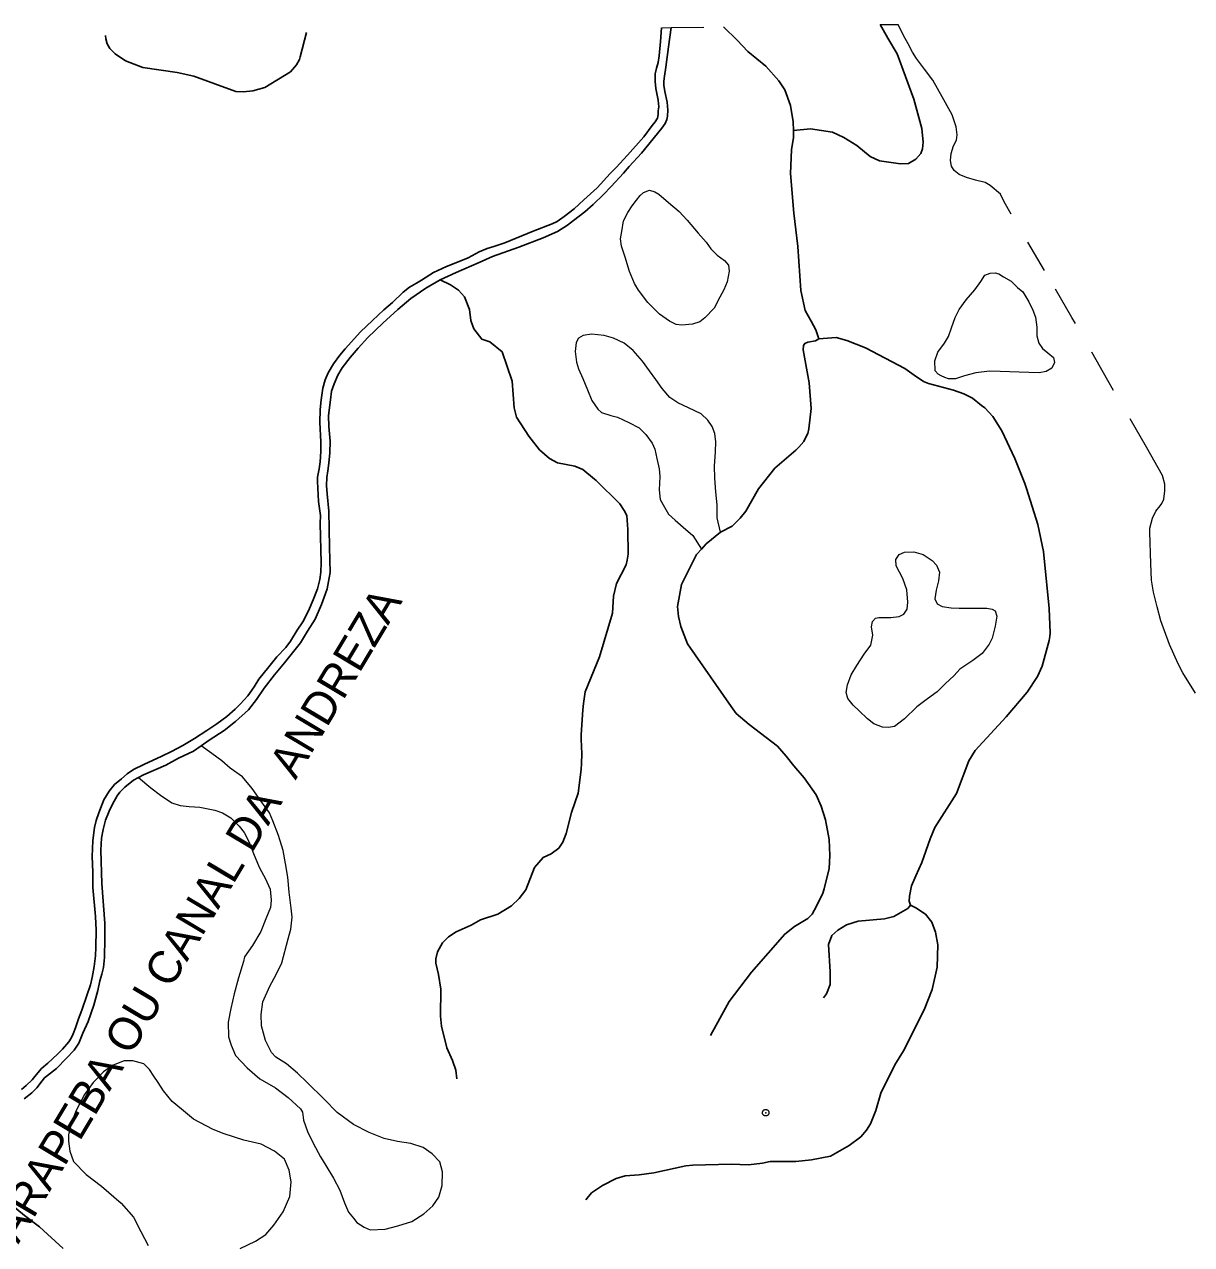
# Model space of a CAD drawing. Extents: x 267.7 to 296, y 7537.7 to 7565.8.
# Drawn here: x 278.742 to 282.305, y 7561.905 to 7565.628 of the extents above; entities that cross this region are included whole.
import ezdxf
from ezdxf.enums import TextEntityAlignment as Align

# ---------------------------------------------------------------- set-up
doc = ezdxf.new("R2010")
doc.units = 0
doc.header["$LTSCALE"] = 0.04
doc.header["$PDMODE"] = 32
doc.header["$PDSIZE"] = 0.02
doc.linetypes.add('SHORT_DASHED', pattern=[2.7, 1.5, -1.2])
for name, color, linetype, lineweight in [('2', 7, 'Continuous', 25), ('21', 7, 'SHORT_DASHED', 13), ('62', 7, 'SHORT_DASHED', 13), ('7', 7, 'Continuous', 25)]:
    doc.layers.add(name, color=color, linetype=linetype, lineweight=lineweight)
doc.layers.add('61', color=7, linetype='Continuous')

msp = doc.modelspace()

# ---------------------------------------------------------------- linework, layer by layer
at = {"layer": '2'}
for points in [[(280.6871, 7565.6181), (280.6839, 7565.5761), (280.6797, 7565.5324), (280.6765, 7565.5116), (280.6711, 7565.4946), (280.6674, 7565.4776), (280.6669, 7565.4541), (280.669, 7565.4323), (280.6765, 7565.3966), (280.6781, 7565.3769), (280.677, 7565.3646), (280.677, 7565.3534), (280.6743, 7565.3422), (280.6669, 7565.3305), (280.6584, 7565.3193), (280.6323, 7565.2852), (280.5827, 7565.2293), (280.548, 7565.1917), (280.5305, 7565.1728), (280.4905, 7565.1297), (280.4501, 7565.0924), (280.4202, 7565.0652), (280.3893, 7565.0423), (280.3685, 7565.0269), (280.3531, 7565.0199), (280.295, 7564.997), (280.2082, 7564.9619), (280.1752, 7564.9507), (280.1544, 7564.9448), (280.1304, 7564.9342), (280.0963, 7564.916), (280.0585, 7564.9006), (280.0303, 7564.8894), (279.9903, 7564.8708), (279.9546, 7564.8478), (279.9392, 7564.8388), (279.9178, 7564.826), (279.8981, 7564.8116), (279.8656, 7564.7797), (279.839, 7564.7573), (279.8044, 7564.7248), (279.7681, 7564.6896), (279.7207, 7564.6379), (279.7053, 7564.6193), (279.6856, 7564.5921), (279.6696, 7564.565), (279.66, 7564.5431), (279.6531, 7564.5186), (279.6483, 7564.4829), (279.6445, 7564.4526), (279.644, 7564.4131), (279.6467, 7564.3545), (279.6467, 7564.3252), (279.6451, 7564.2933), (279.6413, 7564.272), (279.6371, 7564.2469), (279.6366, 7564.2331), (279.6398, 7564.1723), (279.6456, 7564.1292), (279.6451, 7564.1047), (279.6477, 7563.9848), (279.6472, 7563.9571), (279.644, 7563.9342), (279.6366, 7563.9054), (279.6238, 7563.8719), (279.6094, 7563.8383), (279.5918, 7563.8047), (279.5748, 7563.7792), (279.554, 7563.7461), (279.5396, 7563.7264), (279.513, 7563.6982), (279.4879, 7563.6678), (279.4576, 7563.63), (279.4437, 7563.6071), (279.424, 7563.5794), (279.4021, 7563.5549), (279.3856, 7563.5384), (279.3595, 7563.5165), (279.3297, 7563.4936), (279.2993, 7563.4734), (279.2615, 7563.4494), (279.2253, 7563.4276), (279.1906, 7563.4094), (279.1613, 7563.3956), (279.107, 7563.37), (279.0756, 7563.354), (279.0553, 7563.3413), (279.0383, 7563.3263), (279.0175, 7563.3088), (279.0005, 7563.2885), (278.985, 7563.2624), (278.969, 7563.2219), (278.961, 7563.1985), (278.9562, 7563.1772), (278.9514, 7563.1383)], [(280.7159, 7565.6185), (280.7084, 7565.5601), (280.7004, 7565.4978), (280.6962, 7565.4701), (280.6935, 7565.4546), (280.6935, 7565.4424), (280.6972, 7565.4237), (280.7042, 7565.3912), (280.7058, 7565.3667), (280.7047, 7565.3486), (280.7026, 7565.338), (280.6978, 7565.3263), (280.6877, 7565.3119), (280.6259, 7565.2352), (280.588, 7565.1941), (280.5703, 7565.1747), (280.5332, 7565.1339), (280.5097, 7565.1089), (280.4778, 7565.0791), (280.4522, 7565.0562), (280.4186, 7565.03), (280.4, 7565.0157), (280.3696, 7564.9965), (280.3259, 7564.9768), (280.2513, 7564.948), (280.1704, 7564.9198), (280.1299, 7564.9017), (280.0601, 7564.8713), (280.0115, 7564.8483)], [(280.0115, 7564.8483), (279.9674, 7564.8233), (279.9216, 7564.7914), (279.8816, 7564.7583), (279.8363, 7564.7163), (279.79, 7564.6731), (279.7607, 7564.6406), (279.7362, 7564.6118), (279.7117, 7564.5804), (279.6984, 7564.558), (279.6872, 7564.5314), (279.6797, 7564.5085), (279.676, 7564.4824), (279.6707, 7564.4344), (279.6717, 7564.4009), (279.6754, 7564.3561), (279.6744, 7564.3204), (279.6712, 7564.2895), (279.6685, 7564.2661), (279.6648, 7564.2458), (279.6643, 7564.2213), (279.6659, 7564.1952), (279.6712, 7564.143), (279.6738, 7564.0328), (279.6749, 7563.9555), (279.6728, 7563.939), (279.6664, 7563.906), (279.6611, 7563.8916), (279.6488, 7563.858), (279.6291, 7563.8133), (279.6067, 7563.7765), (279.5849, 7563.7408), (279.5359, 7563.6795), (279.5055, 7563.6438), (279.4741, 7563.6028), (279.4506, 7563.5677), (279.4256, 7563.5368), (279.3867, 7563.5011), (279.3521, 7563.4739), (279.3057, 7563.4435), (279.2817, 7563.427)], [(279.2817, 7563.427), (279.2578, 7563.4105), (279.212, 7563.3892), (279.1736, 7563.3679), (279.1059, 7563.3386), (279.0908, 7563.3303)], [(279.0908, 7563.3303), (279.0756, 7563.3221), (279.0489, 7563.3002), (279.033, 7563.2858), (279.0255, 7563.2741), (279.0111, 7563.2491), (279.0005, 7563.2272), (278.9898, 7563.1995), (278.9829, 7563.1713), (278.9776, 7563.1452), (278.9749, 7563.1084), (278.9786, 7563.0067), (278.9871, 7562.8852), (278.9877, 7562.8394), (278.9861, 7562.7803), (278.9839, 7562.7499), (278.9786, 7562.7297), (278.9722, 7562.7094), (278.9658, 7562.6801), (278.9536, 7562.6354), (278.9365, 7562.5853), (278.9205, 7562.5501), (278.9078, 7562.5192), (278.8939, 7562.4985), (278.871, 7562.4734), (278.8396, 7562.4425), (278.8033, 7562.4137), (278.7964, 7562.4047), (278.7804, 7562.3834), (278.765, 7562.3674), (278.7415, 7562.3498)], [(278.9514, 7563.1383), (278.9493, 7563.0893), (278.9514, 7563.0413), (278.9509, 7562.9944), (278.9589, 7562.906), (278.961, 7562.8644)], [(278.961, 7562.8644), (278.9605, 7562.8122), (278.9594, 7562.7856), (278.9552, 7562.7536), (278.9493, 7562.7195), (278.9435, 7562.6972), (278.9328, 7562.6652), (278.9174, 7562.6204), (278.9072, 7562.5938), (278.8982, 7562.5666), (278.8907, 7562.5475), (278.8849, 7562.5347), (278.8779, 7562.523), (278.8587, 7562.5011), (278.8433, 7562.4862), (278.814, 7562.4585), (278.7943, 7562.442), (278.7783, 7562.4223), (278.7655, 7562.4074), (278.7474, 7562.3898), (278.7336, 7562.3781)]]:
    msp.add_lwpolyline(points, dxfattribs=at)
at = {"layer": '21'}
for points in [[(281.5716, 7565.1961), (281.569, 7565.2129), (281.5707, 7565.234), (281.5775, 7565.2575), (281.5867, 7565.2752), (281.5892, 7565.2912), (281.5859, 7565.3156), (281.5741, 7565.3518), (281.5438, 7565.4073), (281.5152, 7565.4578), (281.4899, 7565.4914), (281.4647, 7565.5243), (281.4529, 7565.5436), (281.4395, 7565.5689), (281.4252, 7565.5941), (281.4091, 7565.6282)], [(281.6751, 7565.1456), (281.6456, 7565.1532), (281.6178, 7565.1608), (281.5951, 7565.17), (281.58, 7565.1826), (281.5716, 7565.1961)], [(282.3163, 7563.5872), (282.2784, 7563.6495), (282.2641, 7563.6773), (282.2372, 7563.7362), (282.2111, 7563.8085), (282.2001, 7563.8506), (282.1884, 7563.8952), (282.1825, 7563.9322), (282.1799, 7563.9836), (282.1774, 7564.0786), (282.1774, 7564.0913), (282.185, 7564.1216), (282.1959, 7564.1426), (282.2085, 7564.1594), (282.2136, 7564.1666), (282.2201, 7564.1799), (282.2227, 7564.2049), (282.2227, 7564.2253), (282.2162, 7564.2512), (282.1669, 7564.3377), (282.0492, 7564.5412), (281.9394, 7564.7342), (281.8562, 7564.8776), (281.7323, 7565.0864), (281.721, 7565.1097), (281.6897, 7565.1361), (281.6751, 7565.1456)], [(280.8672, 7564.0791), (280.8571, 7564.1229), (280.8571, 7564.1625), (280.8527, 7564.2021), (280.8498, 7564.2431), (280.8483, 7564.2798), (280.8513, 7564.3237), (280.8527, 7564.3545), (280.8498, 7564.3795), (280.841, 7564.4014), (280.8278, 7564.4205), (280.8073, 7564.4396), (280.7692, 7564.4586), (280.7369, 7564.4733), (280.712, 7564.4894), (280.6885, 7564.5173), (280.6695, 7564.5451), (280.6504, 7564.5715), (280.6284, 7564.6008), (280.6006, 7564.6331), (280.5727, 7564.6551), (280.5405, 7564.6712), (280.5112, 7564.6785), (280.473, 7564.6829), (280.4481, 7564.6785), (280.4334, 7564.6712), (280.4261, 7564.658), (280.4232, 7564.6302), (280.4276, 7564.5979), (280.4334, 7564.5774), (280.4466, 7564.5481), (280.4613, 7564.5129), (280.4745, 7564.4806), (280.4921, 7564.4542), (280.5038, 7564.444), (280.5317, 7564.4352), (280.5522, 7564.4293), (280.5874, 7564.4132), (280.6182, 7564.397), (280.6387, 7564.3765), (280.6578, 7564.3501), (280.6666, 7564.3325), (280.6724, 7564.3032), (280.6797, 7564.2724), (280.6812, 7564.249), (280.6797, 7564.2079), (280.6827, 7564.1786), (280.6959, 7564.1551), (280.7076, 7564.1332), (280.7281, 7564.1156), (280.7531, 7564.0936), (280.7824, 7564.0686), (280.8084, 7564.0269)], [(279.7973, 7561.9502), (279.8431, 7561.9515), (279.8824, 7561.9619), (279.9242, 7561.975), (279.9609, 7561.9986), (279.9884, 7562.0234), (280.0067, 7562.0496), (280.0172, 7562.085), (280.0185, 7562.1268), (280.0106, 7562.1569), (279.9871, 7562.1818), (279.9596, 7562.2014), (279.9216, 7562.2132), (279.881, 7562.2198), (279.8405, 7562.2289), (279.7947, 7562.2472), (279.7462, 7562.2708), (279.6965, 7562.3074), (279.6573, 7562.348), (279.6049, 7562.3991), (279.5761, 7562.4279), (279.5421, 7562.4566), (279.5094, 7562.4763), (279.4963, 7562.4907), (279.478, 7562.5273), (279.4662, 7562.5718), (279.4649, 7562.6072), (279.4701, 7562.6451), (279.491, 7562.6935), (279.5107, 7562.7289), (279.5277, 7562.7642), (279.5473, 7562.8375), (279.5552, 7562.8676), (279.5591, 7562.9042), (279.5565, 7562.9317), (279.5499, 7562.9801), (279.546, 7563.026), (279.5395, 7563.0678), (279.5316, 7563.1071), (279.5172, 7563.1529), (279.5002, 7563.1974), (279.4897, 7563.2223), (279.4636, 7563.2589), (279.4374, 7563.2969), (279.4073, 7563.3322), (279.3706, 7563.3584), (279.3445, 7563.3806), (279.3144, 7563.4029), (279.2817, 7563.427)], [(279.0908, 7563.3303), (279.1285, 7563.2982), (279.1573, 7563.2759), (279.1926, 7563.2524), (279.2175, 7563.2445), (279.245, 7563.2419), (279.2777, 7563.2393), (279.3235, 7563.2301), (279.3471, 7563.2223), (279.3719, 7563.2066), (279.3981, 7563.1817), (279.4125, 7563.1621), (279.4269, 7563.1346), (279.4439, 7563.0927), (279.457, 7563.0613), (279.4609, 7563.0521), (279.4766, 7563.0233), (279.4923, 7562.9893), (279.495, 7562.9553), (279.4937, 7562.933), (279.4793, 7562.899), (279.4636, 7562.8597), (279.4387, 7562.8179), (279.4138, 7562.7825), (279.4112, 7562.7681), (279.3955, 7562.7184), (279.3824, 7562.67), (279.3719, 7562.6255), (279.3641, 7562.5836), (279.3654, 7562.5391), (279.3733, 7562.5129), (279.3863, 7562.4815), (279.4217, 7562.4436), (279.4609, 7562.4108), (279.5081, 7562.3834), (279.5473, 7562.3533), (279.5853, 7562.3192), (279.5905, 7562.3088), (279.5944, 7562.2839), (279.6062, 7562.2499), (279.6232, 7562.2145), (279.6455, 7562.1726), (279.6625, 7562.1465), (279.686, 7562.1072), (279.7044, 7562.0706), (279.7188, 7562.0326), (279.7318, 7562.0038), (279.7462, 7561.9855), (279.7567, 7561.9724), (279.779, 7561.958), (279.7973, 7561.9502)], [(279.4009, 7561.8924), (279.4477, 7561.9149), (279.4795, 7561.9355), (279.5039, 7561.9636), (279.532, 7562.0048), (279.5526, 7562.0516), (279.5563, 7562.0965), (279.5507, 7562.1321), (279.5357, 7562.1658), (279.5058, 7562.1901), (279.4646, 7562.2107), (279.4121, 7562.2238), (279.3522, 7562.2426), (279.3185, 7562.2557), (279.2586, 7562.2875), (279.2212, 7562.3175), (279.1931, 7562.3418), (279.1669, 7562.3736), (279.15, 7562.3998), (279.1369, 7562.4186), (279.1238, 7562.4392), (279.1069, 7562.456), (279.0732, 7562.4654), (279.047, 7562.4654), (279.0133, 7562.4523), (278.9834, 7562.4317), (278.9515, 7562.3998), (278.9253, 7562.3624), (278.8991, 7562.3118), (278.886, 7562.2763), (278.8766, 7562.2407), (278.8766, 7562.2201), (278.8804, 7562.1901), (278.8916, 7562.1583), (278.9309, 7562.119), (278.9777, 7562.0834), (279.0377, 7562.031), (279.0751, 7561.9879), (279.0976, 7561.9448), (279.12, 7561.9018)]]:
    msp.add_lwpolyline(points, dxfattribs=at)
for points in [[(280.6803, 7564.7437), (280.6453, 7564.7794), (280.6169, 7564.8168), (280.6047, 7564.838), (280.5893, 7564.8745), (280.5763, 7564.9176), (280.5649, 7564.9518), (280.5616, 7564.9737), (280.5658, 7564.9964), (280.5709, 7565.0292), (280.5835, 7565.0544), (280.5974, 7565.0746), (280.61, 7565.0922), (280.6213, 7565.1061), (280.6314, 7565.1149), (280.6503, 7565.1225), (280.6667, 7565.1175), (280.6781, 7565.1099), (280.7083, 7565.0847), (280.7411, 7565.0569), (280.7651, 7565.0305), (280.7991, 7564.9914), (280.8231, 7564.9636), (280.8369, 7564.9434), (280.8571, 7564.9245), (280.8786, 7564.9081), (280.8912, 7564.893), (280.8937, 7564.8754), (280.8874, 7564.8426), (280.8773, 7564.8186), (280.8647, 7564.7959), (280.847, 7564.7619), (280.8193, 7564.7329), (280.8042, 7564.7203), (280.7815, 7564.7139), (280.7487, 7564.7102), (280.731, 7564.7127), (280.7108, 7564.7228)], [(281.5403, 7564.5558), (281.5312, 7564.5604), (281.5221, 7564.5713), (281.5212, 7564.6013), (281.5303, 7564.6276), (281.5503, 7564.6558), (281.563, 7564.6757), (281.5721, 7564.7021), (281.583, 7564.7339), (281.5948, 7564.7584), (281.6166, 7564.7875), (281.6429, 7564.8183), (281.6611, 7564.8438), (281.6738, 7564.8628), (281.6902, 7564.8692), (281.7047, 7564.8701), (281.7165, 7564.8674), (281.7301, 7564.8583), (281.7538, 7564.8447), (281.7728, 7564.8256), (281.7892, 7564.812), (281.8082, 7564.7811), (281.8201, 7564.7557), (281.8282, 7564.7348), (281.8319, 7564.7039), (281.8319, 7564.6776), (281.8382, 7564.6558), (281.8491, 7564.6394), (281.8655, 7564.6258), (281.8827, 7564.6122), (281.8864, 7564.5967), (281.8782, 7564.5795), (281.8609, 7564.5686), (281.8391, 7564.5649), (281.8082, 7564.5658), (281.7201, 7564.5695), (281.6874, 7564.5704), (281.6457, 7564.5649), (281.6112, 7564.5558), (281.5839, 7564.5468), (281.563, 7564.5468), (281.5512, 7564.5504)], [(281.3151, 7563.5094), (281.2905, 7563.534), (281.2717, 7563.5504), (281.2553, 7563.5715), (281.2506, 7563.5891), (281.2541, 7563.6125), (281.2658, 7563.643), (281.2834, 7563.6723), (281.3057, 7563.7062), (281.3256, 7563.7344), (281.3315, 7563.7648), (281.3279, 7563.7894), (281.3303, 7563.8058), (281.3397, 7563.8164), (281.3502, 7563.8187), (281.3865, 7563.8187), (281.4123, 7563.8211), (281.4264, 7563.8281), (281.4369, 7563.8433), (281.4381, 7563.8656), (281.4357, 7563.9031), (281.4229, 7563.9371), (281.4029, 7563.9757), (281.4018, 7563.9957), (281.4123, 7564.0109), (281.4287, 7564.0179), (281.4568, 7564.0191), (281.485, 7564.0109), (281.5131, 7563.9921), (281.526, 7563.9781), (281.5353, 7563.957), (281.5318, 7563.93), (281.5248, 7563.9019), (281.5213, 7563.875), (281.5283, 7563.8597), (281.5435, 7563.8515), (281.5705, 7563.848), (281.5951, 7563.8469), (281.6314, 7563.8469), (281.6795, 7563.8469), (281.6959, 7563.8433), (281.7052, 7563.8387), (281.7099, 7563.8222), (281.7052, 7563.7918), (281.6959, 7563.7555), (281.6865, 7563.7367), (281.6654, 7563.7086), (281.6373, 7563.6875), (281.5974, 7563.6606), (281.5799, 7563.6418), (281.5529, 7563.616), (281.5283, 7563.5914), (281.499, 7563.5703), (281.4662, 7563.5457), (281.4287, 7563.5094), (281.3983, 7563.486), (281.3795, 7563.4825), (281.3608, 7563.4836), (281.335, 7563.4942)]]:
    msp.add_lwpolyline(points, close=True, dxfattribs=at)
msp.add_point((281.0048, 7562.3072), dxfattribs=at)
at = {"layer": '62'}
for p, q in [((280.6871, 7565.6181), (280.7159, 7565.6185)), ((280.7159, 7565.6185), (280.8761, 7565.6207))]:
    msp.add_line(p, q, dxfattribs=at)
msp.add_lwpolyline([(281.3537, 7565.6274), (281.4005, 7565.6281), (281.4091, 7565.6282)], dxfattribs=at)
at = {"layer": '7'}
for points in [[(279.6029, 7565.6031), (279.5835, 7565.5295), (279.5813, 7565.5213), (279.5723, 7565.505), (279.5543, 7565.4834), (279.4755, 7565.4361), (279.4398, 7565.4255), (279.4106, 7565.4225), (279.3878, 7565.4239), (279.2594, 7565.4703), (279.208, 7565.4813), (279.1032, 7565.497), (279.051, 7565.5172), (279.0191, 7565.5386), (279.0026, 7565.5547), (278.9947, 7565.5685), (278.991, 7565.5842), (278.9893, 7565.5944)], [(281.0895, 7565.3043), (281.0889, 7565.3313), (281.0807, 7565.3806), (281.063, 7565.4281), (281.0449, 7565.456), (281.0048, 7565.5007), (280.9504, 7565.5458), (280.9176, 7565.5802), (280.8761, 7565.6207)], [(281.3537, 7565.6274), (281.3779, 7565.5861), (281.4059, 7565.5383), (281.4567, 7565.3997), (281.4818, 7565.3103), (281.4855, 7565.2689), (281.4838, 7565.2484), (281.4779, 7565.2338), (281.4625, 7565.2174), (281.441, 7565.204), (281.4164, 7565.203), (281.3517, 7565.2122), (281.3239, 7565.2247), (281.2829, 7565.2584), (281.2433, 7565.2833), (281.2082, 7565.2991), (281.141, 7565.3092), (281.0895, 7565.3043)], [(281.1669, 7564.6689), (281.1582, 7564.696), (281.1437, 7564.7221), (281.1253, 7564.7553), (281.1124, 7564.8165), (281.1028, 7564.9501), (281.0903, 7565.0521), (281.0808, 7565.1736), (281.0834, 7565.2459), (281.0899, 7565.2826), (281.0895, 7565.3043)], [(280.0615, 7562.4101), (280.0594, 7562.4368), (280.0492, 7562.4666), (280.0319, 7562.5056), (280.0153, 7562.5716), (280.0126, 7562.602), (280.0133, 7562.6842), (280.0061, 7562.7293), (279.9979, 7562.7632), (279.9978, 7562.7765), (280.003, 7562.7981), (280.0184, 7562.8258), (280.0369, 7562.8437), (280.06, 7562.8594), (280.106, 7562.8795), (280.134, 7562.8961), (280.1869, 7562.9131), (280.2289, 7562.9387), (280.2524, 7562.9613), (280.2722, 7562.987), (280.2993, 7563.0553), (280.3119, 7563.0711), (280.3253, 7563.0855), (280.3499, 7563.0968), (280.3737, 7563.1148), (280.3858, 7563.1327), (280.3958, 7563.1587), (280.4115, 7563.2231), (280.4325, 7563.282), (280.4414, 7563.3545), (280.4422, 7563.3728), (280.4436, 7563.4021), (280.4418, 7563.4474), (280.4413, 7563.4607), (280.4469, 7563.5362), (280.4483, 7563.5557), (280.4539, 7563.5912), (280.4979, 7563.6988), (280.5373, 7563.8318), (280.5398, 7563.8837), (280.5498, 7563.9216), (280.5789, 7563.979), (280.5816, 7563.993), (280.5851, 7564.0113), (280.5843, 7564.0864), (280.5804, 7564.1298), (280.5727, 7564.145), (280.5593, 7564.1653), (280.4873, 7564.2361), (280.4818, 7564.2407), (280.4463, 7564.27), (280.4225, 7564.2799), (280.3688, 7564.2903), (280.3448, 7564.3033), (280.3148, 7564.3295), (280.2822, 7564.3715), (280.2443, 7564.4292), (280.2375, 7564.458), (280.2308, 7564.54), (280.2, 7564.629), (280.1629, 7564.6599), (280.138, 7564.6674), (280.1134, 7564.6992), (280.1055, 7564.7211), (280.1043, 7564.7245), (280.1011, 7564.7586), (280.0855, 7564.7973), (280.0669, 7564.817), (280.0428, 7564.8331), (280.0115, 7564.8483)], [(280.8672, 7564.0791), (280.9021, 7564.0975), (280.9269, 7564.1211), (280.944, 7564.1431), (280.9823, 7564.2108), (281.0331, 7564.2737), (281.0963, 7564.3294), (281.1059, 7564.3378), (281.1207, 7564.3552), (281.1245, 7564.3628), (281.1331, 7564.3798), (281.1366, 7564.3941), (281.1435, 7564.4557), (281.1371, 7564.5344), (281.1195, 7564.6347), (281.1197, 7564.6487), (281.1238, 7564.6549), (281.1331, 7564.659), (281.1567, 7564.6631), (281.1669, 7564.6689)], [(281.4465, 7562.9403), (281.443, 7562.9531), (281.4441, 7562.9675), (281.4502, 7562.9993), (281.4625, 7563.0301), (281.481, 7563.0711), (281.5067, 7563.143), (281.5213, 7563.1778), (281.5872, 7563.281), (281.6247, 7563.3811), (281.6437, 7563.4129), (281.7384, 7563.5151), (281.8024, 7563.5905), (281.8347, 7563.6381), (281.8488, 7563.6694), (281.8703, 7563.7477), (281.8719, 7563.76), (281.8735, 7563.7717), (281.8704, 7563.846), (281.8528, 7564.0201), (281.8351, 7564.1017), (281.8009, 7564.2124), (281.7956, 7564.2272), (281.792, 7564.2371), (281.7653, 7564.3039), (281.7253, 7564.388), (281.698, 7564.4312), (281.6731, 7564.4583), (281.6639, 7564.4655), (281.6355, 7564.4877), (281.609, 7564.5013), (281.5775, 7564.5122), (281.5015, 7564.5327), (281.4866, 7564.5388), (281.4574, 7564.5574), (281.4298, 7564.5783), (281.309, 7564.6413), (281.2527, 7564.664), (281.2199, 7564.6729), (281.1669, 7564.6689)], [(280.8084, 7564.0269), (280.8156, 7564.0346), (280.8233, 7564.0429), (280.8672, 7564.0791)], [(280.8362, 7562.5427), (280.8933, 7562.6465), (280.961, 7562.7362), (281.0629, 7562.8522), (281.0928, 7562.8749), (281.133, 7562.8995), (281.1466, 7562.9129), (281.1601, 7562.9375), (281.1788, 7562.9774), (281.1831, 7562.9904), (281.198, 7563.052), (281.2005, 7563.0916), (281.1988, 7563.1409), (281.1875, 7563.2005), (281.1736, 7563.243), (281.1587, 7563.2774), (281.1217, 7563.3291), (281.091, 7563.3657), (281.0672, 7563.395), (281.0407, 7563.4252), (280.9545, 7563.492), (280.9142, 7563.5258), (280.8993, 7563.5471), (280.7662, 7563.7381), (280.746, 7563.7912), (280.7383, 7563.8214), (280.7351, 7563.8519), (280.7481, 7563.9186), (280.7934, 7564.0109), (280.8084, 7564.0269)], [(280.4558, 7562.041), (280.4731, 7562.0622), (280.5067, 7562.0852), (280.548, 7562.1063), (280.5757, 7562.1145), (280.6185, 7562.1172), (280.663, 7562.1238), (280.7611, 7562.1449), (280.782, 7562.1474), (280.8991, 7562.1501), (280.9521, 7562.1482), (280.9945, 7562.1535), (281.0184, 7562.1578), (281.0965, 7562.1585), (281.1441, 7562.1633), (281.2023, 7562.1742), (281.2234, 7562.1864), (281.2593, 7562.2069), (281.2951, 7562.2339), (281.3126, 7562.2535), (281.3247, 7562.2737), (281.3412, 7562.3135), (281.3561, 7562.3672), (281.3985, 7562.4536), (281.4256, 7562.4963), (281.488, 7562.6206), (281.5125, 7562.6831), (281.5276, 7562.7512), (281.5299, 7562.8193), (281.5235, 7562.8579), (281.5123, 7562.8888), (281.4926, 7562.9127), (281.4633, 7562.9327), (281.4465, 7562.9403)], [(281.181, 7562.6573), (281.1901, 7562.6695), (281.2016, 7562.6982), (281.2016, 7562.7367), (281.1961, 7562.8206), (281.2071, 7562.8482), (281.2248, 7562.8644), (281.2516, 7562.8806), (281.2873, 7562.8915), (281.3671, 7562.8986), (281.396, 7562.9056), (281.4381, 7562.9304), (281.4465, 7562.9403)], [(278.8606, 7561.8928), (278.7877, 7561.9585), (278.7425, 7561.9934), (278.6656, 7562.056)]]:
    msp.add_lwpolyline(points, dxfattribs=at)

# ---------------------------------------------------------------- texts
at = {"layer": '61'}
msp.add_text('RIO CARAPEBA OU CANAL DA  ANDREZA', height=0.1, rotation=59.138, dxfattribs=at).set_placement((279.2153, 7562.7274), align=Align.CENTER)

doc.saveas('drawing.dxf')
